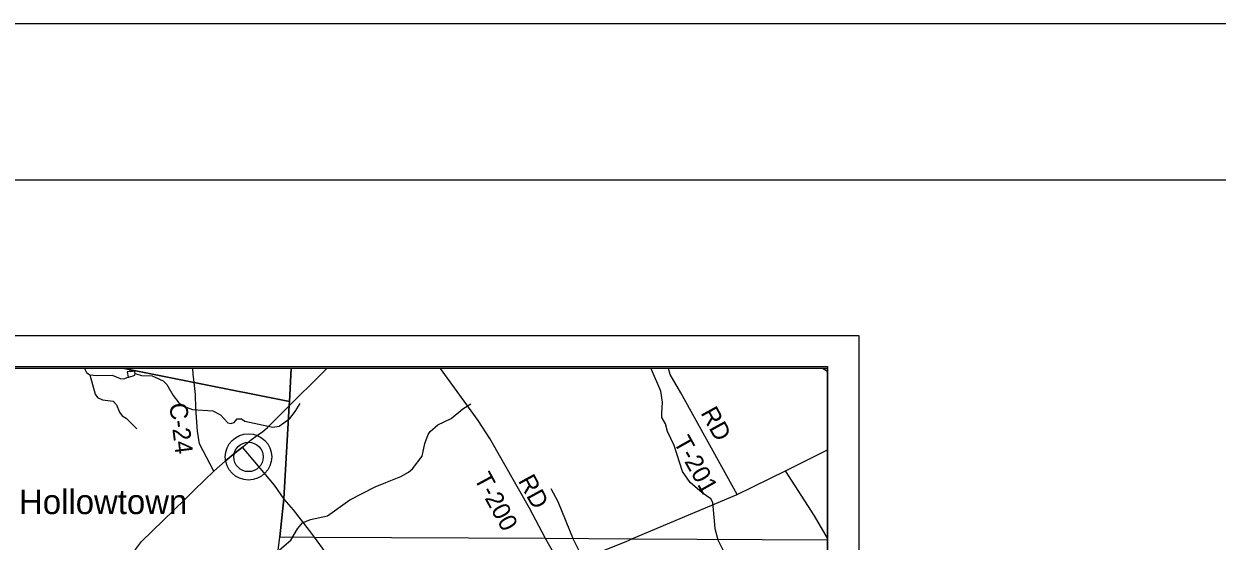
# Model space of a CAD drawing. Extents: x 0 to 34, y 0 to 22.
# Drawn here: x 6.32 to 10.15, y 20.34 to 22 of the extents above; entities that cross this region are included whole.
import ezdxf

# ---------------------------------------------------------------- set-up
doc = ezdxf.new("R2010")
doc.units = 0
for name, color, linetype in [('Default', 7, 'Continuous'), ('GM_X_County_Road', 7, 'Continuous'), ('GM_X_County_Road_Text', 7, 'Continuous'), ('GM_X_Minor_Lake', 7, 'Continuous'), ('GM_X_Minor_River', 7, 'Continuous'), ('GM_X_State_Route', 7, 'Continuous'), ('GM_X_Township_Road', 7, 'Continuous'), ('GM_X_Township_Road_Text', 7, 'Continuous'), ('GM_X_Unincorporated', 7, 'Continuous'), ('GM_X_Unincorporated_Location', 7, 'Continuous'), ('GM_X_Unincorporated_Text', 7, 'Continuous'), ('SH_Border', 7, 'Continuous'), ('SH_Cut_Line', 7, 'Continuous'), ('SH_Data', 7, 'Continuous')]:
    doc.layers.add(name, color=color, linetype=linetype)

msp = doc.modelspace()

# ---------------------------------------------------------------- linework, layer by layer
at = {"layer": 'Default'}
msp.add_lwpolyline([(6.7802, 17.4233), (6.9652, 18.9204), (7.0779, 19.8324), (7.1423, 20.3535), (7.155, 20.4756), (7.1718, 20.7748), (7.1725, 20.7885), (6.8666, 20.8494), (6.6419, 20.8941), (2.4006, 20.8941), (2.3791, 20.1601), (2.3212, 18.6531), (2.2797, 17.8302)], dxfattribs=at)
for points in [[(7.1785, 20.8941), (6.6419, 20.8941), (6.8666, 20.8494), (7.1725, 20.7885)], [(8.9, 20.3443), (8.9, 20.8941), (7.1785, 20.8941), (7.1725, 20.7885), (7.1718, 20.7748), (7.155, 20.4756), (7.1423, 20.3535), (7.2527, 20.3529), (7.9945, 20.3491), (8.2716, 20.3476)]]:
    msp.add_lwpolyline(points, close=True, dxfattribs=at)
at = {"layer": 'GM_X_County_Road'}
msp.add_line((7.022, 20.6419), (6.9987, 20.623), dxfattribs=at)
for points in [[(6.8714, 20.8108), (6.8669, 20.8489), (6.8637, 20.8756), (6.8625, 20.8941)], [(6.9295, 20.564), (6.8839, 20.6518), (6.8771, 20.6932), (6.8727, 20.7671), (6.8716, 20.8096), (6.8714, 20.8108)], [(6.9987, 20.623), (6.9661, 20.5964), (6.9295, 20.564)], [(7.3101, 20.275), (7.2529, 20.3524), (7.2367, 20.3746), (7.186, 20.4403), (7.1552, 20.475), (7.1245, 20.5198), (7.022, 20.6419)], [(8.2608, 20.3425), (8.2718, 20.3471), (8.6098, 20.4895), (8.7651, 20.566), (8.9, 20.6325)], [(7.5213, 20.0286), (8.0456, 20.2555), (8.2553, 20.3401), (8.2608, 20.3425)]]:
    msp.add_lwpolyline(points, dxfattribs=at)
at = {"layer": 'GM_X_Minor_Lake'}
for points in [[(6.6548, 20.8665), (6.6567, 20.8661), (6.6639, 20.8678), (6.6712, 20.8704), (6.6762, 20.8729), (6.6778, 20.8778), (6.6767, 20.8828), (6.6741, 20.8851), (6.6692, 20.8844), (6.6631, 20.8845), (6.6582, 20.8843), (6.6521, 20.8832)], [(6.6521, 20.8832), (6.6548, 20.8665)]]:
    msp.add_lwpolyline(points, dxfattribs=at)
at = {"layer": 'GM_X_Minor_River'}
msp.add_line((8.9, 20.8844), (8.8839, 20.8941), dxfattribs=at)
for points in [[(6.515, 20.8941), (6.5216, 20.8813), (6.5324, 20.8739), (6.5555, 20.8716), (6.6034, 20.8731), (6.629, 20.862), (6.6407, 20.861), (6.6548, 20.8665)], [(6.5324, 20.8739), (6.5496, 20.8114), (6.5562, 20.801), (6.5728, 20.7935), (6.6064, 20.7888), (6.618, 20.7776), (6.6275, 20.7543), (6.636, 20.7423), (6.6491, 20.7345), (6.6834, 20.7009)], [(6.6778, 20.8778), (6.6978, 20.871), (6.7323, 20.8705), (6.7676, 20.8543), (6.7788, 20.8431), (6.7994, 20.8071), (6.818, 20.784), (6.8326, 20.7727), (6.8612, 20.762), (6.9272, 20.7586), (6.9516, 20.7453), (6.9751, 20.7194), (6.9849, 20.717), (6.9956, 20.7206), (7.0052, 20.7329), (7.0185, 20.7323), (7.0294, 20.7249), (7.1189, 20.7056), (7.1402, 20.709), (7.174, 20.7331), (7.1915, 20.7559), (7.2071, 20.7818)], [(8.572, 20.2955), (8.5487, 20.3433), (8.5386, 20.3795), (8.5377, 20.3931), (8.5315, 20.4638), (8.5248, 20.4756), (8.4974, 20.4946), (8.4584, 20.5282), (8.4346, 20.5631), (8.4069, 20.6465), (8.3859, 20.692), (8.3794, 20.716), (8.3683, 20.7366), (8.3677, 20.7507), (8.3701, 20.7859), (8.3649, 20.8209), (8.3348, 20.8904), (8.3337, 20.8941)], [(7.53, 20.5478), (7.5553, 20.5611), (7.568, 20.5715), (7.599, 20.6123), (7.6069, 20.6531), (7.6184, 20.6822), (7.6243, 20.6923), (7.6486, 20.7131), (7.6914, 20.7333), (7.7287, 20.7641), (7.7544, 20.7811)], [(7.1409, 20.3117), (7.1771, 20.3426), (7.1982, 20.379), (7.2149, 20.3985), (7.2405, 20.4098), (7.2946, 20.4214), (7.3664, 20.4725), (7.4479, 20.5144), (7.4819, 20.5278), (7.53, 20.5478)], [(8.1086, 20.296), (8.0839, 20.3449), (8.0347, 20.4666), (8.0129, 20.5079)]]:
    msp.add_lwpolyline(points, dxfattribs=at)
at = {"layer": 'GM_X_State_Route'}
msp.add_line((6.9987, 20.623), (7.022, 20.6419), dxfattribs=at)
for points in [[(7.143, 20.7456), (7.172, 20.7743), (7.1807, 20.7829), (7.2667, 20.8679), (7.2932, 20.8941)], [(7.022, 20.6419), (7.0465, 20.6629), (7.0748, 20.6834), (7.0864, 20.6907), (7.102, 20.705), (7.143, 20.7456)], [(6.9295, 20.564), (6.9661, 20.5964), (6.9987, 20.623)], [(6.2956, 19.9604), (6.4341, 20.0826), (6.4833, 20.1299), (6.5043, 20.1498), (6.6785, 20.3128), (6.6982, 20.3384), (6.8371, 20.4739), (6.8679, 20.505), (6.9295, 20.564)]]:
    msp.add_lwpolyline(points, dxfattribs=at)
at = {"layer": 'GM_X_Township_Road'}
for points in [[(8.0227, 20.2987), (7.9947, 20.3485), (7.9434, 20.4455), (7.816, 20.6694), (7.7783, 20.7267), (7.6571, 20.8941)], [(8.6098, 20.4895), (8.4291, 20.8162), (8.3944, 20.8745), (8.3892, 20.8941)], [(8.9, 20.3496), (8.8579, 20.4215), (8.7651, 20.566)]]:
    msp.add_lwpolyline(points, dxfattribs=at)
at = {"layer": 'GM_X_Unincorporated'}
for radius in [0.0744, 0.0472]:
    msp.add_circle((7.0413, 20.6102), radius, dxfattribs=at)
at = {"layer": 'GM_X_Unincorporated_Location'}
msp.add_line((7.0413, 20.6102), (7.0413, 20.6102), dxfattribs=at)
at = {"layer": 'SH_Border'}
msp.add_lwpolyline([(1.5, 21.5), (33.5, 21.5), (33.5, 0.5), (1.5, 0.5)], close=True, dxfattribs=at)
at = {"layer": 'SH_Cut_Line'}
msp.add_lwpolyline([(0, 0), (34, 0), (34, 22), (0, 22)], close=True, dxfattribs=at)
msp.add_lwpolyline([(8.9, 14.2922), (8.9, 20.8941), (2.4006, 20.8941), (2.3791, 20.1601), (2.3212, 18.6531), (2.2797, 17.8302)], dxfattribs=at)
at = {"layer": 'SH_Data'}
for p, q in [((2, 21), (9, 21)), ((9, 21), (9, 14)), ((2.1, 20.9), (8.9, 20.9)), ((8.9, 20.9), (8.9, 14.1))]:
    msp.add_line(p, q, dxfattribs=at)

# ---------------------------------------------------------------- texts
at = {"layer": 'GM_X_County_Road_Text'}
msp.add_text('C-24', height=0.05682, rotation=277.2099, dxfattribs=at).set_placement((6.7868, 20.7802))
at = {"layer": 'GM_X_Township_Road_Text'}
for s, rotation, p in [('RD', 298.7673, (8.491, 20.7517)), ('T-201', 299.3271, (8.4038, 20.6585)), ('T-200', 298.4532, (7.7639, 20.5414)), ('RD', 298.5713, (7.9052, 20.5341))]:
    msp.add_text(s, height=0.05682, rotation=rotation, dxfattribs=at).set_placement(p)
at = {"layer": 'GM_X_Unincorporated_Text'}
msp.add_text('Hollowtown', height=0.07898, rotation=0, dxfattribs=at).set_placement((6.3048, 20.4267))

doc.saveas('drawing.dxf')
